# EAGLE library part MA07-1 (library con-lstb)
PIN HEADER
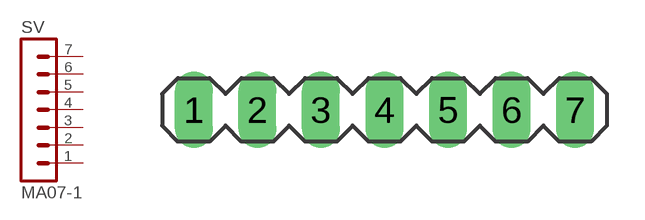
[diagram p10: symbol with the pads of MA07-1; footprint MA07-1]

Designator prefix SV

## MA07-1 (OC_FARNELL: unknown; OC_NEWARK: unknown)  [MA07-1]
1  1  pas
2  2  pas
3  3  pas
4  4  pas
5  5  pas
6  6  pas
7  7  pas

## Footprint MA07-1 (pad centres in mm)
PIN HEADER
drill 1.016 long: 1 -7.62,0; 2 -5.08,0; 3 -2.54,0; 4 0,0; 5 2.54,0; 6 5.08,0; 7 7.62,0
